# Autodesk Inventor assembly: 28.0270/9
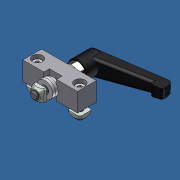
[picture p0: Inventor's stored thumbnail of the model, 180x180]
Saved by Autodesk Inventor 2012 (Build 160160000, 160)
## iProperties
Created: 2011-02
Part Number: 28.0270/9
Document SubType Name: Assembly
Designer: Administrator
Description: SLIDE CLAMPING UNIT 5mm OFFSET
Vendor: S
Author: Administrator
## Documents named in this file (3)
- C:\Andys Backup Data\ANDY'S INVENTOR\INVENTOR LIBRARIES\PARTS LIBRARY\COMPONENTS LR\28.0270_9 SLIDE CLAMPING UNIT 5mm OFFSET..iam
- C:\Andys Backup Data\ANDY'S INVENTOR\INVENTOR LIBRARIES\PARTS LIBRARY\COMPONENTS LR\SUBCOMPONENTS\28.0270 SLIDE CLAMPING UNIT 5mm OFFSET.iam
- C:\Andys Backup Data\ANDY'S INVENTOR\INVENTOR LIBRARIES\PARTS LIBRARY\FASTENING ELEMENTS\SET SCREWS\21.9841 M4X5 FLAT POINT DIN 913.ipt
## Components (2 placed, 2 different names)
1. 28.0270 SLIDE CLAMPING UNIT 5mm OFFSET:1 [sub-assembly] — Tangent:1, Mate:1
2. 21.9841 SET SCREW M4X5 FLAT POINT DIN 913:1 — Tangent:1, Mate:1
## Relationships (2: Tangent 1, Mate 1)
- Tangent:1: 28.0270 SLIDE CLAMPING UNIT 5mm OFFSET:1 ↔ 21.9841 SET SCREW M4X5 FLAT POINT DIN 913:1
- Mate:1: 28.0270 SLIDE CLAMPING UNIT 5mm OFFSET:1 ↔ 21.9841 SET SCREW M4X5 FLAT POINT DIN 913:1
